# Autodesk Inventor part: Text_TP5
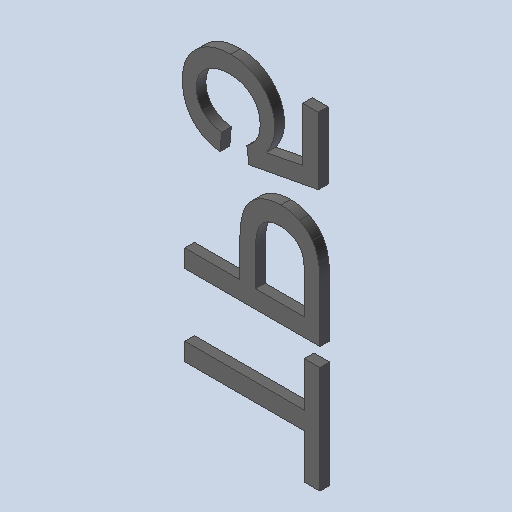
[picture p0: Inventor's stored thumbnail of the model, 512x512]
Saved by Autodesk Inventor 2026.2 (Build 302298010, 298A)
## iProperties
Created: 2026-10
Part Number: Text_TP5
Material: Générique
Document SubType Name: Modeling
Designer: mel
Density: 1 g/cm^3
Appearance: Par défaut
Author: mel
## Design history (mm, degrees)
feature "Base1"
feature "Base2"
feature "Base3"
node "Solide1"
node "Solide2"
node "Solide3"
